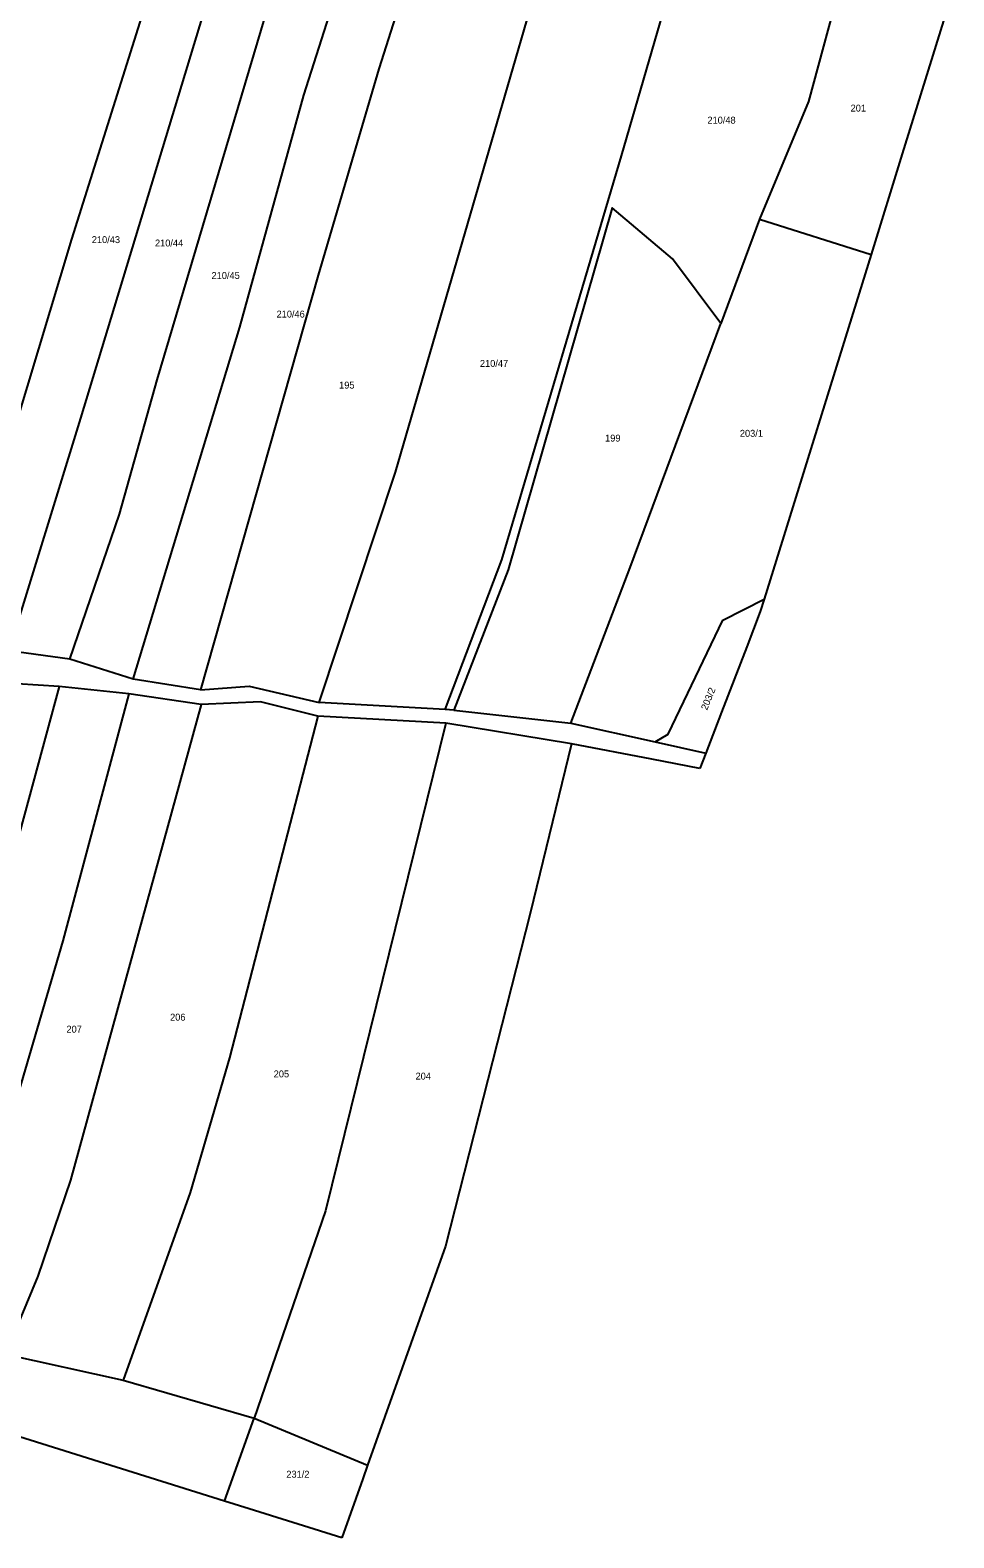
# Model space of a CAD drawing. Extents: x -746176 to -739709, y -1128407 to -1124482.
# Drawn here: x -742474.2 to -742246.8, y -1127907.2 to -1127536.1 of the extents above; entities that cross this region are included whole.
import ezdxf

# ---------------------------------------------------------------- set-up
doc = ezdxf.new("R2010")
doc.units = 0
doc.layers.add('Vrstva 33', color=7, linetype='Continuous')
doc.layers.add('Vrstva 42', color=7, linetype='Continuous')

msp = doc.modelspace()

# ---------------------------------------------------------------- linework, layer by layer
at = {"layer": 'Vrstva 33'}
for p, q in [((-742246.84, -1127525.71), (-742259.53, -1127566.57)), ((-742259.53, -1127566.57), (-742267.21, -1127591.32)), ((-742294.71, -1127582.66), (-742304.21, -1127608.28)), ((-742294.71, -1127582.66), (-742267.21, -1127591.32)), ((-742267.21, -1127591.32), (-742293.55, -1127676.19)), ((-742293.55, -1127676.19), (-742294.48, -1127679.19)), ((-742294.48, -1127679.19), (-742297.82, -1127687.89)), ((-742464.41, -1127690.97), (-742479.32, -1127688.85)), ((-742297.82, -1127687.89), (-742304, -1127703.97)), ((-742448.8, -1127695.84), (-742464.41, -1127690.97)), ((-742467.04, -1127697.67), (-742483.38, -1127696.63)), ((-742432.3, -1127698.48), (-742448.8, -1127695.84)), ((-742449.94, -1127699.44), (-742467.04, -1127697.67)), ((-742432.12, -1127702.08), (-742449.94, -1127699.44)), ((-742371.88, -1127706.65), (-742403.42, -1127704.93)), ((-742372.01, -1127703.32), (-742403.02, -1127701.6)), ((-742369.9, -1127703.45), (-742372.01, -1127703.32)), ((-742369.9, -1127703.45), (-742341.09, -1127706.66)), ((-742304, -1127703.97), (-742307.87, -1127714.04)), ((-742340.92, -1127711.81), (-742371.88, -1127706.65)), ((-742341.09, -1127706.66), (-742320.38, -1127711.26)), ((-742321.14, -1127715.58), (-742340.92, -1127711.81)), ((-742320.38, -1127711.26), (-742307.87, -1127714.04)), ((-742309.33, -1127717.84), (-742321.14, -1127715.58)), ((-742307.87, -1127714.04), (-742309.33, -1127717.84)), ((-742480.24, -1127862.01), (-742451.26, -1127868.39)), ((-742451.26, -1127868.39), (-742419.07, -1127877.77)), ((-742426.38, -1127898.15), (-742491.5, -1127877.75)), ((-742426.38, -1127898.15), (-742419.07, -1127877.77)), ((-742419.07, -1127877.77), (-742391.12, -1127889.33)), ((-742391.12, -1127889.33), (-742392.3, -1127892.65)), ((-742392.3, -1127892.65), (-742397.46, -1127907.21)), ((-742420.31, -1127900.05), (-742426.38, -1127898.15)), ((-742397.46, -1127907.21), (-742420.31, -1127900.05))]:
    msp.add_line(p, q, dxfattribs=at)
for points in [[(-742494, -1127687.08), (-742463.97, -1127587.54), (-742428.89, -1127476.24)], [(-742479.32, -1127688.85), (-742461.68, -1127631.58), (-742415.87, -1127480.36)], [(-742464.41, -1127690.97), (-742452.19, -1127655.25), (-742442.95, -1127622.18), (-742402.15, -1127485.01)], [(-742448.8, -1127695.84), (-742422.61, -1127609.18), (-742406.86, -1127552.13), (-742387.37, -1127491.14)], [(-742373.12, -1127497.63), (-742388.36, -1127545.64), (-742403.33, -1127596.39), (-742432.3, -1127698.48)], [(-742403.02, -1127701.6), (-742384.25, -1127644.88), (-742343.44, -1127504.37)], [(-742372.01, -1127703.32), (-742358.1, -1127666.45), (-742328.66, -1127567.04), (-742312.99, -1127513.08), (-742313.1, -1127510.34)], [(-742274.2, -1127522.4), (-742282.6, -1127553.63), (-742294.71, -1127582.66)], [(-742304.21, -1127608.28), (-742316.12, -1127592.36), (-742330.9, -1127579.81), (-742356.55, -1127668.96), (-742369.9, -1127703.45)], [(-742341.09, -1127706.66), (-742326.47, -1127668.34), (-742304.21, -1127608.28)], [(-742320.38, -1127711.26), (-742317.14, -1127709.37), (-742303.66, -1127681.35), (-742293.55, -1127676.19)], [(-742432.3, -1127698.48), (-742420.3, -1127697.56), (-742403.02, -1127701.6)], [(-742467.04, -1127697.67), (-742480.9, -1127748.82), (-742494.32, -1127803.6), (-742511.96, -1127847.84)], [(-742449.94, -1127699.44), (-742466.13, -1127760.26), (-742485.77, -1127826.93), (-742498.72, -1127857.52)], [(-742432.12, -1127702.08), (-742464.27, -1127819.17), (-742472.32, -1127842.8), (-742480.24, -1127862.01)], [(-742403.42, -1127704.93), (-742425.12, -1127789.08), (-742434.82, -1127822.21), (-742451.26, -1127868.39)], [(-742403.42, -1127704.93), (-742417.48, -1127701.42), (-742432.12, -1127702.08)], [(-742371.88, -1127706.65), (-742401.48, -1127826.73), (-742419.07, -1127877.77)], [(-742340.92, -1127711.81), (-742351.14, -1127753.54), (-742371.99, -1127835.4), (-742391.12, -1127889.33)]]:
    msp.add_lwpolyline(points, dxfattribs=at)

# ---------------------------------------------------------------- texts
at = {"layer": 'Vrstva 42'}
for s, p in [('201', (-742272.25, -1127556.14)), ('210/48', (-742307.5, -1127559.11)), ('210/43', (-742459.02, -1127588.52)), ('210/44', (-742443.47, -1127589.35)), ('210/45', (-742429.55, -1127597.35)), ('210/46', (-742413.55, -1127606.84)), ('210/47', (-742363.49, -1127618.99)), ('195', (-742398.15, -1127624.33)), ('203/1', (-742299.51, -1127636.19)), ('199', (-742332.68, -1127637.37)), ('206', (-742439.75, -1127779.9)), ('207', (-742465.26, -1127782.86)), ('205', (-742414.25, -1127793.87)), ('204', (-742379.34, -1127794.41)), ('231/2', (-742411.14, -1127892.4))]:
    msp.add_text(s, height=1.7, dxfattribs=at).set_placement(p)
msp.add_text('203/2', height=1.7, rotation=68, dxfattribs=at).set_placement((-742307.58, -1127703.62))

doc.saveas('drawing.dxf')
